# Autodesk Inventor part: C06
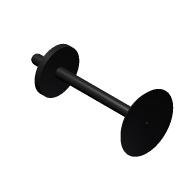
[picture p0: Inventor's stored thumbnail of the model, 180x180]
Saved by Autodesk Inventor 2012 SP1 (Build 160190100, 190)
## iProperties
Created: 2006-02
Part Number: C06
Document SubType Name: Modeling
Material: Stainless Steel, 440C
Mass: 49.0738 g
Surface Area: 50.6933 cm^2
Volume: 6.3321 cm^3
Density: 7.75 g/cm^3
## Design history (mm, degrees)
sketch "Sketch1"
  geometry: L1 (-77, 3)-(-65, 3); L2 (-65, 3)-(-65, 14); L3 (-2, 8.5)-(-2, 16.5); L4 (-2, 16.5)-(0, 18.5); L5 (0, 18.5)-(0, 0); L6 (-80, 0)-(0, 0); L7 (-143, 0)-(39, 0) reference; L8 (0, 24.95)-(0, -5.15) reference; L9 (-61.5, 14)-(-61.5, 3); L10 (-61.5, 3)-(-7.5, 3); L11 (-65, 14)-(-61.5, 14); A1 r 3 centre (-77, 0) between (-77, 3) and (-80, 0); A2 r 5.5 centre (-7.5, 8.5) between (-7.5, 3) and (-2, 8.5)
  constraints: 18 end point, 5 point on line, 4 point on circle, 3 perpendicular, 3 tangent, 2 centre point, 1 collinear, 1 parallel
  dimensions: "d2" = 18.5 distance of L4.end L5.end; "d5" = 2 distance between parallel lines of L3 L5; "d6" = 135 deg angle of L5 L4; "d7" = 8 distance of L3.start L3.end; "d11" = 12 distance of L1.start L1.end; "d12" = 3 radius of A1; "d13" = 80 distance of L6.start L5.end; "d14" = 11 distance of L1.end L2.end; "d15" = 3.5 distance of L2.end L9.start
revolve "Revolution1" sketch "Sketch1" stored, may be unused: angle "d0" = 90 deg
workplane "Work Plane1"
workplane "Work Plane2"
sketch "Sketch2"
  geometry: C1 r 3 at (-77, 0); 2 further points
  constraints: 1 centre point, 1 coincident
body "Solid1"
